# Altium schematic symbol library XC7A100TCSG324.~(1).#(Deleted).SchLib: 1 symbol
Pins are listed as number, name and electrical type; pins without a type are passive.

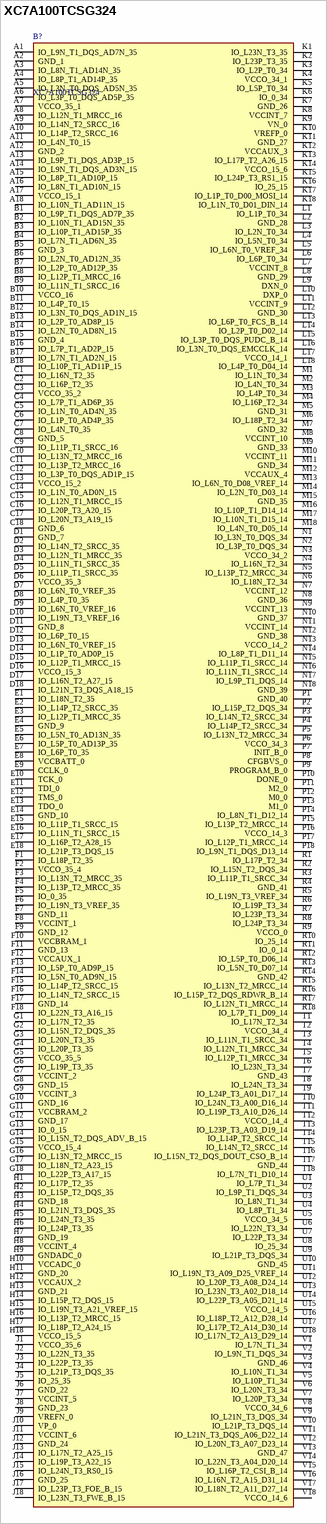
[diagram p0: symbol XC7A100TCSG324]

## XC7A100TCSG324
designator B?
Artix-7 Wire-Bond Chip-Scale BGA (0.8 mm Pitch); Manufacturer_Name: AMD; Geometry.Height: 1.5mm
footprint BGA324C80P18X18_1500X1500X150
pins: A1 IO_L9N_T1_DQS_AD7N_35, A2 GND_1, A3 IO_L8N_T1_AD14N_35, A4 IO_L8P_T1_AD14P_35, A5 IO_L3N_T0_DQS_AD5N_35, A6 IO_L3P_T0_DQS_AD5P_35, A7 VCCO_35_1, A8 IO_L12N_T1_MRCC_16, A9 IO_L14N_T2_SRCC_16, A10 IO_L14P_T2_SRCC_16, A11 IO_L4N_T0_15, A12 GND_2, A13 IO_L9P_T1_DQS_AD3P_15, A14 IO_L9N_T1_DQS_AD3N_15, A15 IO_L8P_T1_AD10P_15, A16 IO_L8N_T1_AD10N_15, A17 VCCO_15_1, A18 IO_L10N_T1_AD11N_15, B1 IO_L9P_T1_DQS_AD7P_35, B2 IO_L10N_T1_AD15N_35, B3 IO_L10P_T1_AD15P_35, B4 IO_L7N_T1_AD6N_35, B5 GND_3, B6 IO_L2N_T0_AD12N_35, B7 IO_L2P_T0_AD12P_35, B8 IO_L12P_T1_MRCC_16, B9 IO_L11N_T1_SRCC_16, B10 VCCO_16, B11 IO_L4P_T0_15, B12 IO_L3N_T0_DQS_AD1N_15, B13 IO_L2P_T0_AD8P_15, B14 IO_L2N_T0_AD8N_15, B15 GND_4, B16 IO_L7P_T1_AD2P_15, B17 IO_L7N_T1_AD2N_15, B18 IO_L10P_T1_AD11P_15, C1 IO_L16N_T2_35, C2 IO_L16P_T2_35, C3 VCCO_35_2, C4 IO_L7P_T1_AD6P_35, C5 IO_L1N_T0_AD4N_35, C6 IO_L1P_T0_AD4P_35, C7 IO_L4N_T0_35, C8 GND_5, C9 IO_L11P_T1_SRCC_16, C10 IO_L13N_T2_MRCC_16, C11 IO_L13P_T2_MRCC_16, C12 IO_L3P_T0_DQS_AD1P_15, C13 VCCO_15_2, C14 IO_L1N_T0_AD0N_15, C15 IO_L12N_T1_MRCC_15, C16 IO_L20P_T3_A20_15, C17 IO_L20N_T3_A19_15, C18 GND_6, D1 GND_7, D2 IO_L14N_T2_SRCC_35, D3 IO_L12N_T1_MRCC_35, D4 IO_L11N_T1_SRCC_35, D5 IO_L11P_T1_SRCC_35, D6 VCCO_35_3, D7 IO_L6N_T0_VREF_35, D8 IO_L4P_T0_35, D9 IO_L6N_T0_VREF_16, D10 IO_L19N_T3_VREF_16, D11 GND_8, D12 IO_L6P_T0_15, D13 IO_L6N_T0_VREF_15, D14 IO_L1P_T0_AD0P_15, D15 IO_L12P_T1_MRCC_15, D16 VCCO_15_3, D17 IO_L16N_T2_A27_15, D18 IO_L21N_T3_DQS_A18_15, E1 IO_L18N_T2_35, E2 IO_L14P_T2_SRCC_35, E3 IO_L12P_T1_MRCC_35, E4 GND_9, E5 IO_L5N_T0_AD13N_35, E6 IO_L5P_T0_AD13P_35, E7 IO_L6P_T0_35, E8 VCCBATT_0, E9 CCLK_0, E10 TCK_0, E11 TDI_0, E12 TMS_0, E13 TDO_0, E14 GND_10, E15 IO_L11P_T1_SRCC_15, E16 IO_L11N_T1_SRCC_15, E17 IO_L16P_T2_A28_15, E18 IO_L21P_T3_DQS_15, F1 IO_L18P_T2_35, F2 VCCO_35_4, F3 IO_L13N_T2_MRCC_35, F4 IO_L13P_T2_MRCC_35, F5 IO_0_35, F6 IO_L19N_T3_VREF_35, F7 GND_11, F8 VCCINT_1, F9 GND_12, F10 VCCBRAM_1, F11 GND_13, F12 VCCAUX_1, F13 IO_L5P_T0_AD9P_15, F14 IO_L5N_T0_AD9N_15, F15 IO_L14P_T2_SRCC_15, F16 IO_L14N_T2_SRCC_15, F17 GND_14, F18 IO_L22N_T3_A16_15, G1 IO_L17N_T2_35, G2 IO_L15N_T2_DQS_35, G3 IO_L20N_T3_35, G4 IO_L20P_T3_35, G5 VCCO_35_5, G6 IO_L19P_T3_35, G7 VCCINT_2, G8 GND_15, G9 VCCINT_3, G10 GND_16, G11 VCCBRAM_2, G12 GND_17, G13 IO_0_15, G14 IO_L15N_T2_DQS_ADV_B_15, G15 VCCO_15_4, G16 IO_L13N_T2_MRCC_15, G17 IO_L18N_T2_A23_15, G18 IO_L22P_T3_A17_15, H1 IO_L17P_T2_35, H2 IO_L15P_T2_DQS_35, H3 GND_18, H4 IO_L21N_T3_DQS_35, H5 IO_L24N_T3_35, H6 IO_L24P_T3_35, H7 GND_19, H8 VCCINT_4, H9 GNDADC_0, H10 VCCADC_0, H11 GND_20, H12 VCCAUX_2, H13 GND_21, H14 IO_L15P_T2_DQS_15, H15 IO_L19N_T3_A21_VREF_15, H16 IO_L13P_T2_MRCC_15, H17 IO_L18P_T2_A24_15, H18 VCCO_15_5, J1 VCCO_35_6, J2 IO_L22N_T3_35, J3 IO_L22P_T3_35, J4 IO_L21P_T3_DQS_35, J5 IO_25_35, J6 GND_22, J7 VCCINT_5, J8 GND_23, J9 VREFN_0, J10 VP_0, J11 VCCINT_6, J12 GND_24, J13 IO_L17N_T2_A25_15, J14 IO_L19P_T3_A22_15, J15 IO_L24N_T3_RS0_15, J16 GND_25, J17 IO_L23P_T3_FOE_B_15, J18 IO_L23N_T3_FWE_B_15, K1 IO_L23N_T3_35, K2 IO_L23P_T3_35, K3 IO_L2P_T0_34, K4 VCCO_34_1, K5 IO_L5P_T0_34, K6 IO_0_34, K7 GND_26, K8 VCCINT_7, K9 VN_0, K10 VREFP_0, K11 GND_27, K12 VCCAUX_3, K13 IO_L17P_T2_A26_15, K14 VCCO_15_6, K15 IO_L24P_T3_RS1_15, K16 IO_25_15, K17 IO_L1P_T0_D00_MOSI_14, K18 IO_L1N_T0_D01_DIN_14, L1 IO_L1P_T0_34, L2 GND_28, L3 IO_L2N_T0_34, L4 IO_L5N_T0_34, L5 IO_L6N_T0_VREF_34, L6 IO_L6P_T0_34, L7 VCCINT_8, L8 GND_29, L9 DXN_0, L10 DXP_0, L11 VCCINT_9, L12 GND_30, L13 IO_L6P_T0_FCS_B_14, L14 IO_L2P_T0_D02_14, L15 IO_L3P_T0_DQS_PUDC_B_14, L16 IO_L3N_T0_DQS_EMCCLK_14, L17 VCCO_14_1, L18 IO_L4P_T0_D04_14, M1 IO_L1N_T0_34, M2 IO_L4N_T0_34, M3 IO_L4P_T0_34, M4 IO_L16P_T2_34, M5 GND_31, M6 IO_L18P_T2_34, M7 GND_32, M8 VCCINT_10, M9 GND_33, M10 VCCINT_11, M11 GND_34, M12 VCCAUX_4, M13 IO_L6N_T0_D08_VREF_14, M14 IO_L2N_T0_D03_14, M15 GND_35, M16 IO_L10P_T1_D14_14, M17 IO_L10N_T1_D15_14, M18 IO_L4N_T0_D05_14, N1 IO_L3N_T0_DQS_34, N2 IO_L3P_T0_DQS_34, N3 VCCO_34_2, N4 IO_L16N_T2_34, N5 IO_L13P_T2_MRCC_34, N6 IO_L18N_T2_34, N7 VCCINT_12, N8 GND_36, N9 VCCINT_13, N10 GND_37, N11 VCCINT_14, N12 GND_38, N13 VCCO_14_2, N14 IO_L8P_T1_D11_14, N15 IO_L11P_T1_SRCC_14, N16 IO_L11N_T1_SRCC_14, N17 IO_L9P_T1_DQS_14, N18 GND_39, P1 GND_40, P2 IO_L15P_T2_DQS_34, P3 IO_L14N_T2_SRCC_34, P4 IO_L14P_T2_SRCC_34, P5 IO_L13N_T2_MRCC_34, P6 VCCO_34_3, P7 INIT_B_0, P8 CFGBVS_0, P9 PROGRAM_B_0, P10 DONE_0, P11 M2_0, P12 M0_0, P13 M1_0, P14 IO_L8N_T1_D12_14, P15 IO_L13P_T2_MRCC_14, P16 VCCO_14_3, P17 IO_L12P_T1_MRCC_14, P18 IO_L9N_T1_DQS_D13_14, R1 IO_L17P_T2_34, R2 IO_L15N_T2_DQS_34, R3 IO_L11P_T1_SRCC_34, R4 GND_41, R5 IO_L19N_T3_VREF_34, R6 IO_L19P_T3_34, R7 IO_L23P_T3_34, R8 IO_L24P_T3_34, R9 VCCO_0, R10 IO_25_14, R11 IO_0_14, R12 IO_L5P_T0_D06_14, R13 IO_L5N_T0_D07_14, R14 GND_42, R15 IO_L13N_T2_MRCC_14, R16 IO_L15P_T2_DQS_RDWR_B_14, R17 IO_L12N_T1_MRCC_14, R18 IO_L7P_T1_D09_14, T1 IO_L17N_T2_34, T2 VCCO_34_4, T3 IO_L11N_T1_SRCC_34, T4 IO_L12N_T1_MRCC_34, T5 IO_L12P_T1_MRCC_34, T6 IO_L23N_T3_34, T7 GND_43, T8 IO_L24N_T3_34, T9 IO_L24P_T3_A01_D17_14, T10 IO_L24N_T3_A00_D16_14, T11 IO_L19P_T3_A10_D26_14, T12 VCCO_14_4, T13 IO_L23P_T3_A03_D19_14, T14 IO_L14P_T2_SRCC_14, T15 IO_L14N_T2_SRCC_14, T16 IO_L15N_T2_DQS_DOUT_CSO_B_14, T17 GND_44, T18 IO_L7N_T1_D10_14, U1 IO_L7P_T1_34, U2 IO_L9P_T1_DQS_34, U3 IO_L8N_T1_34, U4 IO_L8P_T1_34, U5 VCCO_34_5, U6 IO_L22N_T3_34, U7 IO_L22P_T3_34, U8 IO_25_34, U9 IO_L21P_T3_DQS_34, U10 GND_45, U11 IO_L19N_T3_A09_D25_VREF_14, U12 IO_L20P_T3_A08_D24_14, U13 IO_L23N_T3_A02_D18_14, U14 IO_L22P_T3_A05_D21_14, U15 VCCO_14_5, U16 IO_L18P_T2_A12_D28_14, U17 IO_L17P_T2_A14_D30_14, U18 IO_L17N_T2_A13_D29_14, V1 IO_L7N_T1_34, V2 IO_L9N_T1_DQS_34, V3 GND_46, V4 IO_L10N_T1_34, V5 IO_L10P_T1_34, V6 IO_L20N_T3_34, V7 IO_L20P_T3_34, V8 VCCO_34_6, V9 IO_L21N_T3_DQS_34, V10 IO_L21P_T3_DQS_14, V11 IO_L21N_T3_DQS_A06_D22_14, V12 IO_L20N_T3_A07_D23_14, V13 GND_47, V14 IO_L22N_T3_A04_D20_14, V15 IO_L16P_T2_CSI_B_14, V16 IO_L16N_T2_A15_D31_14, V17 IO_L18N_T2_A11_D27_14, V18 VCCO_14_6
